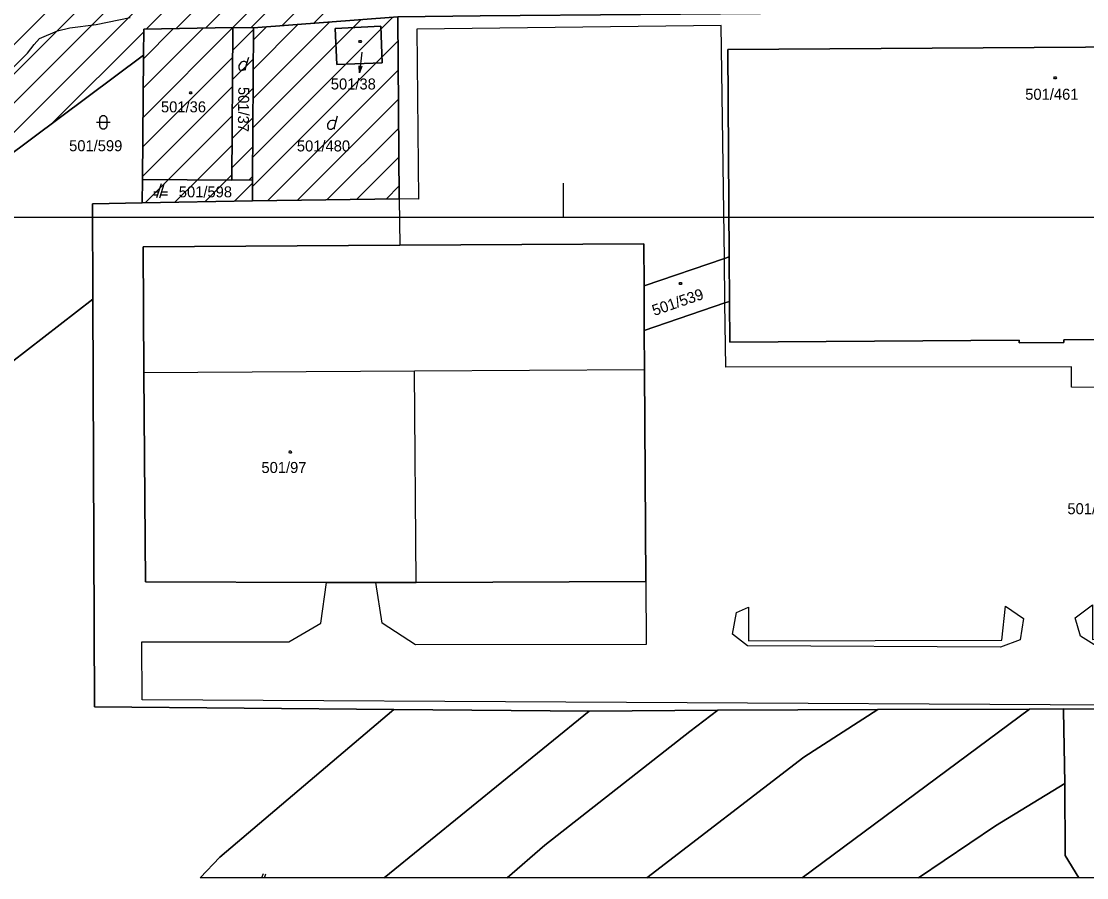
# Model space of a CAD drawing. Extents: x -264309 to -263505, y -1242443 to -1241763.
# Drawn here: x -264079.6 to -263924.7, y -1242443.4 to -1242319 of the extents above; entities that cross this region are included whole.
import ezdxf

# ---------------------------------------------------------------- set-up
doc = ezdxf.new("R2010")
doc.units = 0
for name, color, linetype in [('KN_2019_08_16', 7, 'Continuous'), ('KN_2019_08_16_KLADPAR', 7, 'Continuous'), ('KN_2019_08_16_ZAPPAR', 7, 'Continuous'), ('RAM_NA_TLAC_10xA4_1-500', 7, 'Continuous'), ('SRAFY_PARCELY', 7, 'Continuous')]:
    doc.layers.add(name, color=color, linetype=linetype)

msp = doc.modelspace()

# ---------------------------------------------------------------- linework, layer by layer
at = {"layer": 'KN_2019_08_16'}
msp.add_lwpolyline([(-264080.85, -1242325.81), (-264078.68, -1242323.64), (-264077.73, -1242322.4), (-264076.93, -1242321.5), (-264074.3, -1242320.41), (-264072.53, -1242319.96), (-264068.7, -1242319.48), (-264063.75, -1242318.45)], dxfattribs=at)
at = {"layer": 'KN_2019_08_16_KLADPAR'}
for p, q in [((-264045.81, -1242319.96), (-264045.81, -1242319.96)), ((-264061.82, -1242323.92), (-264061.96, -1242341.99)), ((-264046.8, -1242325.15), (-264046.53, -1242324.25)), ((-264030.11, -1242325.52), (-264030.41, -1242326.49)), ((-264033.89, -1242333.68), (-264033.62, -1242332.78)), ((-264061.96, -1242341.99), (-264061.99, -1242345.41)), ((-264061.99, -1242345.41), (-264061.96, -1242341.99)), ((-264059.65, -1242343.85), (-264060.33, -1242343.85)), ((-264059.23, -1242342.65), (-264059.93, -1242344.65)), ((-264059.43, -1242344.65), (-264058.83, -1242342.65)), ((-264058.33, -1242343.85), (-264059.19, -1242343.85)), ((-264060.33, -1242344.25), (-264059.79, -1242344.25)), ((-264059.31, -1242344.25), (-264058.33, -1242344.25)), ((-263976.69, -1242353.26), (-263976.65, -1242359.72)), ((-263989.04, -1242363.95), (-263989.08, -1242357.47)), ((-264069.2, -1242359.38), (-264068.96, -1242418.63)), ((-264050.73, -1242440.47), (-264025.44, -1242419.01)), ((-263997.04, -1242419.26), (-264026.86, -1242443.45)), ((-264026.86, -1242443.45), (-263997.04, -1242419.26)), ((-264025.44, -1242419.01), (-263997.04, -1242419.26)), ((-263997.04, -1242419.26), (-263978.33, -1242419.1)), ((-263978.33, -1242419.1), (-263982.41, -1242422.21)), ((-263982.41, -1242422.21), (-263978.33, -1242419.1)), ((-263978.33, -1242419.1), (-263955.09, -1242419.03)), ((-263966.11, -1242443.45), (-263933.06, -1242418.97)), ((-263933.06, -1242418.97), (-263966.11, -1242443.45)), ((-263955.09, -1242419.03), (-263965.85, -1242425.95)), ((-263965.85, -1242425.95), (-263955.09, -1242419.03)), ((-263955.09, -1242419.03), (-263933.06, -1242418.97)), ((-263933.06, -1242418.97), (-263928.14, -1242418.9)), ((-263928.14, -1242418.9), (-263928.13, -1242419.18)), ((-263928.13, -1242419.18), (-263928.14, -1242418.9)), ((-263928.14, -1242418.9), (-263899.7, -1242418.94)), ((-263928.13, -1242419.18), (-263927.91, -1242429.77)), ((-263927.91, -1242429.77), (-263928.13, -1242419.18)), ((-263982.41, -1242422.21), (-264003.49, -1242438.71)), ((-264003.49, -1242438.71), (-263982.41, -1242422.21)), ((-263965.85, -1242425.95), (-263988.66, -1242443.45)), ((-263988.66, -1242443.45), (-263965.85, -1242425.95)), ((-263927.91, -1242429.77), (-263937.98, -1242435.92)), ((-263937.98, -1242435.92), (-263927.91, -1242429.77)), ((-263927.91, -1242429.77), (-263927.89, -1242440.22)), ((-263927.89, -1242440.22), (-263927.91, -1242429.77)), ((-263937.98, -1242435.92), (-263949.17, -1242443.45)), ((-263949.17, -1242443.45), (-263937.98, -1242435.92)), ((-264003.49, -1242438.71), (-264008.99, -1242443.45)), ((-264008.99, -1242443.45), (-264003.49, -1242438.71)), ((-264053.6, -1242443.45), (-264050.73, -1242440.47)), ((-263927.89, -1242440.22), (-263925.88, -1242443.45)), ((-263925.88, -1242443.45), (-263927.89, -1242440.22)), ((-264044.45, -1242442.88), (-264044.65, -1242443.45)), ((-264044.22, -1242443.45), (-264044.05, -1242442.88)), ((-264026.86, -1242443.45), (-264053.6, -1242443.45)), ((-264008.99, -1242443.45), (-264026.86, -1242443.45)), ((-263988.66, -1242443.45), (-264008.99, -1242443.45)), ((-263966.11, -1242443.45), (-263988.66, -1242443.45)), ((-263949.17, -1242443.45), (-263966.11, -1242443.45)), ((-263925.88, -1242443.45), (-263949.17, -1242443.45)), ((-263915.82, -1242443.45), (-263925.88, -1242443.45))]:
    msp.add_line(p, q, dxfattribs=at)
for points in [[(-264045.86, -1242306.31), (-263951.37, -1242306.76), (-263951.29, -1242290.6), (-263949.74, -1242287.63), (-263945.92, -1242287.35), (-263946.05, -1242311.56), (-263938.35, -1242311.44), (-263937.4, -1242310.7), (-263937.27, -1242317.62), (-263989.58, -1242318.02), (-264012.87, -1242318.24), (-264024.87, -1242318.35), (-264045.81, -1242319.96), (-264048.82, -1242319.93), (-264044.28, -1242315.26), (-264044.13, -1242307.8)], [(-264045.81, -1242319.96), (-264024.87, -1242318.35), (-264024.64, -1242344.82), (-264045.98, -1242345.11), (-264045.96, -1242342.04)], [(-264048.99, -1242342.09), (-264061.96, -1242341.99), (-264061.82, -1242323.92), (-264061.79, -1242320.14), (-264048.82, -1242319.93)], [(-264048.99, -1242342.09), (-264048.82, -1242319.93), (-264045.81, -1242319.96), (-264045.96, -1242342.04)], [(-264033.95, -1242320.06), (-264033.72, -1242325.32), (-264027.11, -1242325.04), (-264027.34, -1242319.71)], [(-264033.72, -1242325.32), (-264033.95, -1242320.06), (-264027.34, -1242319.71), (-264027.11, -1242325.04)], [(-264030.25, -1242321.82), (-264030.16, -1242321.97), (-264030.25, -1242322.12), (-264030.43, -1242322.12), (-264030.52, -1242321.97), (-264030.43, -1242321.82)], [(-263976.61, -1242365.64), (-263976.65, -1242359.72), (-263976.69, -1242353.26), (-263976.89, -1242323.14), (-263880.39, -1242322.51), (-263880.27, -1242340.53), (-263879.95, -1242340.53), (-263879.9, -1242347.02), (-263880.23, -1242347.02), (-263880.12, -1242365.01), (-263928.07, -1242365.32), (-263928.07, -1242365.67), (-263934.57, -1242365.72), (-263934.57, -1242365.37)], [(-263929.24, -1242327.07), (-263929.15, -1242327.22), (-263929.24, -1242327.37), (-263929.42, -1242327.37), (-263929.51, -1242327.22), (-263929.42, -1242327.07)], [(-264054.88, -1242329.26), (-264054.79, -1242329.41), (-264054.88, -1242329.56), (-264055.06, -1242329.56), (-264055.15, -1242329.41), (-264055.06, -1242329.26)], [(-264068.16, -1242333.2), (-264068.06, -1242332.91), (-264067.81, -1242332.73), (-264067.5, -1242332.73), (-264067.25, -1242332.91), (-264067.15, -1242333.2), (-264067.15, -1242334.2), (-264067.25, -1242334.49), (-264067.5, -1242334.67), (-264067.81, -1242334.67), (-264068.06, -1242334.49), (-264068.16, -1242334.2)], [(-264061.75, -1242370.08), (-264061.87, -1242351.8), (-264024.58, -1242351.56), (-263989.12, -1242351.34), (-263989.08, -1242357.47), (-263989.04, -1242363.95), (-263989.01, -1242369.66), (-263988.83, -1242400.42), (-264022.19, -1242400.57), (-264028.07, -1242400.56), (-264035.24, -1242400.55), (-264061.55, -1242400.48)], [(-263983.68, -1242356.95), (-263983.59, -1242357.1), (-263983.68, -1242357.25), (-263983.86, -1242357.25), (-263983.95, -1242357.1), (-263983.86, -1242356.95)], [(-264040.4, -1242381.45), (-264040.31, -1242381.6), (-264040.4, -1242381.75), (-264040.58, -1242381.75), (-264040.67, -1242381.6), (-264040.58, -1242381.45)]]:
    msp.add_lwpolyline(points, close=True, dxfattribs=at)
for points in [[(-264099.36, -1242306.05), (-264045.86, -1242306.31), (-264044.13, -1242307.8), (-264044.28, -1242315.26), (-264048.82, -1242319.93)], [(-264069.25, -1242345.54), (-264061.99, -1242345.41), (-264045.98, -1242345.11), (-264024.64, -1242344.82), (-264024.87, -1242318.35), (-264012.87, -1242318.24), (-263989.58, -1242318.02), (-263937.27, -1242317.62), (-263930.87, -1242317.54), (-263870.55, -1242316.79)], [(-263870.55, -1242316.79), (-263843.11, -1242332.49), (-263842.59, -1242334.42), (-263866.24, -1242369.43), (-263870.81, -1242376.19), (-263895.05, -1242412.05), (-263899.7, -1242418.94), (-263928.14, -1242418.9), (-263933.06, -1242418.97), (-263955.09, -1242419.03), (-263978.33, -1242419.1), (-263997.04, -1242419.26), (-264025.44, -1242419.01), (-264068.96, -1242418.63), (-264069.2, -1242359.38), (-264069.25, -1242345.54)], [(-264048.82, -1242319.93), (-264061.79, -1242320.14), (-264061.82, -1242323.92)], [(-264030.09, -1242323.51), (-264030.41, -1242326.49), (-264030.5, -1242325.48)], [(-263880.39, -1242322.51), (-263976.89, -1242323.14), (-263976.69, -1242353.26)], [(-263976.65, -1242359.72), (-263976.61, -1242365.64), (-263934.57, -1242365.37), (-263934.57, -1242365.72), (-263928.07, -1242365.67), (-263928.07, -1242365.32), (-263880.12, -1242365.01), (-263880.23, -1242347.02), (-263879.9, -1242347.02), (-263879.95, -1242340.53), (-263880.27, -1242340.53), (-263880.39, -1242322.51)], [(-264155.07, -1242401.25), (-264132.82, -1242380.09), (-264109.99, -1242360.41), (-264082.11, -1242339.09), (-264061.82, -1242323.92)], [(-264061.82, -1242323.92), (-264082.11, -1242339.09), (-264109.99, -1242360.41), (-264132.82, -1242380.09), (-264155.07, -1242401.25)], [(-264046.98, -1242326.14), (-264046.98, -1242325.87), (-264046.8, -1242325.15), (-264046.89, -1242324.97), (-264047.07, -1242324.88), (-264047.34, -1242324.88), (-264047.61, -1242324.97), (-264047.79, -1242325.15), (-264047.97, -1242325.42), (-264047.97, -1242325.78), (-264047.88, -1242326.05), (-264047.7, -1242326.14), (-264047.43, -1242326.14), (-264047.25, -1242326.05), (-264046.98, -1242325.87)], [(-264068.66, -1242333.7), (-264067.39, -1242333.7), (-264066.66, -1242333.7)], [(-264034.07, -1242334.67), (-264034.07, -1242334.4), (-264033.89, -1242333.68), (-264033.98, -1242333.5), (-264034.16, -1242333.41), (-264034.43, -1242333.41), (-264034.7, -1242333.5), (-264034.88, -1242333.68), (-264035.06, -1242333.95), (-264035.06, -1242334.31), (-264034.97, -1242334.58), (-264034.79, -1242334.67), (-264034.52, -1242334.67), (-264034.34, -1242334.58), (-264034.07, -1242334.4)], [(-264061.96, -1242341.99), (-264048.99, -1242342.09), (-264045.96, -1242342.04), (-264045.98, -1242345.11), (-264061.99, -1242345.41)], [(-264061.99, -1242345.41), (-264069.25, -1242345.54), (-264069.2, -1242359.38)], [(-263989.08, -1242357.47), (-263989.12, -1242351.34), (-264024.58, -1242351.56), (-264061.87, -1242351.8), (-264061.75, -1242370.08), (-264061.55, -1242400.48), (-264035.24, -1242400.55), (-264028.07, -1242400.56), (-264022.19, -1242400.57), (-263988.83, -1242400.42), (-263989.01, -1242369.66), (-263989.04, -1242363.95)], [(-263976.69, -1242353.26), (-263977.4, -1242353.5), (-263989.08, -1242357.47)], [(-263989.08, -1242357.47), (-263977.4, -1242353.5), (-263976.69, -1242353.26)], [(-264069.2, -1242359.38), (-264088.24, -1242374.12), (-264137.73, -1242416.49)], [(-264137.73, -1242416.49), (-264088.24, -1242374.12), (-264069.2, -1242359.38)], [(-263989.04, -1242363.95), (-263977.32, -1242359.95), (-263976.65, -1242359.72)], [(-263976.65, -1242359.72), (-263977.32, -1242359.95), (-263989.04, -1242363.95)], [(-264068.96, -1242418.63), (-264025.44, -1242419.01), (-264050.73, -1242440.47), (-264053.6, -1242443.45)]]:
    msp.add_lwpolyline(points, dxfattribs=at)
at = {"layer": 'KN_2019_08_16_ZAPPAR'}
for p, q in [((-263977.86, -1242319.64), (-264022.1, -1242320.14)), ((-263977.4, -1242353.5), (-263977.86, -1242319.64)), ((-264024.64, -1242344.82), (-264024.58, -1242351.56)), ((-263977.32, -1242359.95), (-263977.4, -1242353.5)), ((-263977.19, -1242369.28), (-263977.32, -1242359.95)), ((-264022.45, -1242369.85), (-264061.75, -1242370.08)), ((-263989.01, -1242369.66), (-264022.45, -1242369.85)), ((-264022.19, -1242400.57), (-264022.45, -1242369.85)), ((-263926.93, -1242369.21), (-263977.19, -1242369.28)), ((-263988.83, -1242400.42), (-263988.78, -1242409.56)), ((-263988.78, -1242409.56), (-264022.3, -1242409.64)), ((-263937.28, -1242409.94), (-263974.02, -1242409.77)), ((-263901.26, -1242418.49), (-264062.03, -1242417.63))]:
    msp.add_line(p, q, dxfattribs=at)
for points in [[(-264022.1, -1242320.14), (-264021.83, -1242344.88), (-264024.64, -1242344.82)], [(-263868.44, -1242367.53), (-263872.05, -1242365.41), (-263877.38, -1242372.91), (-263926.94, -1242372.17), (-263926.93, -1242369.21)], [(-264062.03, -1242417.63), (-264062.04, -1242409.19), (-264040.68, -1242409.17), (-264036.07, -1242406.49), (-264035.24, -1242400.55)], [(-264022.3, -1242409.64), (-264027.11, -1242406.49), (-264028.07, -1242400.56)], [(-263974.02, -1242409.77), (-263976.23, -1242408.06), (-263975.64, -1242404.91), (-263973.9, -1242404.13), (-263973.9, -1242409.05), (-263937.07, -1242408.92), (-263936.55, -1242404), (-263933.92, -1242405.79), (-263934.41, -1242408.88), (-263937.28, -1242409.94)], [(-263920.36, -1242409.31), (-263923.3, -1242409.8), (-263925.66, -1242408.34), (-263926.4, -1242405.7), (-263923.88, -1242403.8), (-263923.89, -1242408.83), (-263895.99, -1242408.63)]]:
    msp.add_lwpolyline(points, dxfattribs=at)
at = {"layer": 'RAM_NA_TLAC_10xA4_1-500'}
msp.add_line((-264000.83, -1242342.54), (-264000.83, -1242347.54), dxfattribs=at)
msp.add_lwpolyline([(-264210.83, -1242050.54), (-264105.83, -1242050.54), (-264000.83, -1242050.54), (-263895.83, -1242050.54), (-263790.83, -1242050.54), (-263685.83, -1242050.54), (-263685.83, -1242199.04), (-263685.83, -1242347.54), (-263790.83, -1242347.54), (-263895.83, -1242347.54), (-264000.83, -1242347.54), (-264105.83, -1242347.54), (-264210.83, -1242347.54), (-264210.83, -1242199.04)], close=True, dxfattribs=at)
at = {"layer": 'SRAFY_PARCELY'}
for p, q in [((-264157.42, -1242399.19), (-264064.45, -1242306.22)), ((-264155.16, -1242401.17), (-264060.23, -1242306.24)), ((-264111.2, -1242361.45), (-264056.01, -1242306.26)), ((-264092.67, -1242347.16), (-264051.79, -1242306.28)), ((-264061.4, -1242320.13), (-264047.56, -1242306.3)), ((-264046.23, -1242319.96), (-264032.64, -1242306.37)), ((-264041.67, -1242319.64), (-264028.42, -1242306.39)), ((-264037.07, -1242319.29), (-264024.2, -1242306.41)), ((-264057.08, -1242320.06), (-264044.5, -1242307.48)), ((-264052.77, -1242319.99), (-264044.2, -1242311.43)), ((-264045.94, -1242338.77), (-264025.57, -1242318.4)), ((-264045.91, -1242334.5), (-264030.17, -1242318.76)), ((-264075.14, -1242333.88), (-264061.79, -1242320.53)), ((-264061.89, -1242333.01), (-264048.82, -1242319.94)), ((-264061.86, -1242328.73), (-264053.13, -1242320)), ((-264061.82, -1242324.46), (-264057.44, -1242320.07)), ((-264061.79, -1242320.18), (-264061.75, -1242320.14)), ((-264048.85, -1242323.22), (-264045.81, -1242320.19)), ((-264045.88, -1242330.23), (-264034.76, -1242319.11)), ((-264045.85, -1242325.96), (-264039.36, -1242319.46)), ((-264045.82, -1242321.69), (-264043.95, -1242319.82)), ((-264045.97, -1242343.04), (-264024.84, -1242321.92)), ((-264061.92, -1242337.28), (-264048.85, -1242324.21)), ((-264048.88, -1242327.5), (-264045.84, -1242324.46)), ((-264043.76, -1242345.08), (-264024.8, -1242326.12)), ((-264061.96, -1242341.56), (-264048.89, -1242328.49)), ((-264048.91, -1242331.78), (-264045.87, -1242328.73)), ((-264039.46, -1242345.02), (-264024.77, -1242330.33)), ((-264058.17, -1242342.02), (-264048.92, -1242332.76)), ((-264048.94, -1242336.05), (-264045.9, -1242333.01)), ((-264035.16, -1242344.96), (-264024.73, -1242334.53)), ((-264053.96, -1242342.05), (-264048.95, -1242337.04)), ((-264048.98, -1242340.33), (-264045.93, -1242337.28)), ((-264030.86, -1242344.9), (-264024.69, -1242338.74)), ((-264061.57, -1242345.4), (-264058.19, -1242342.02)), ((-264057.25, -1242345.32), (-264053.98, -1242342.05)), ((-264052.92, -1242345.24), (-264049.77, -1242342.08)), ((-264049.75, -1242342.08), (-264048.98, -1242341.31)), ((-264046.46, -1242342.05), (-264045.96, -1242341.55)), ((-264048.6, -1242345.16), (-264045.96, -1242342.52)), ((-264026.56, -1242344.85), (-264024.66, -1242342.95))]:
    msp.add_line(p, q, dxfattribs=at)

# ---------------------------------------------------------------- texts
at = {"layer": 'KN_2019_08_16_KLADPAR'}
for s, p in [('501/38', (-264034.6, -1242328.93)), ('501/461', (-263933.68, -1242330.42)), ('501/36', (-264059.28, -1242332.25)), ('501/599', (-264072.63, -1242337.9)), ('501/480', (-264039.53, -1242337.93)), ('501/598', (-264056.69, -1242344.6)), ('501/97', (-264044.68, -1242384.65)), ('501/117', (-263927.55, -1242390.64))]:
    msp.add_text(s, height=1.6, dxfattribs=at).set_placement(p)
for s, rotation, p in [('501/37', 269.3475, (-264048.04, -1242328.55)), ('501/539', 19.0795, (-263987.58, -1242361.84))]:
    msp.add_text(s, height=1.6, rotation=rotation, dxfattribs=at).set_placement(p)

doc.saveas('drawing.dxf')
